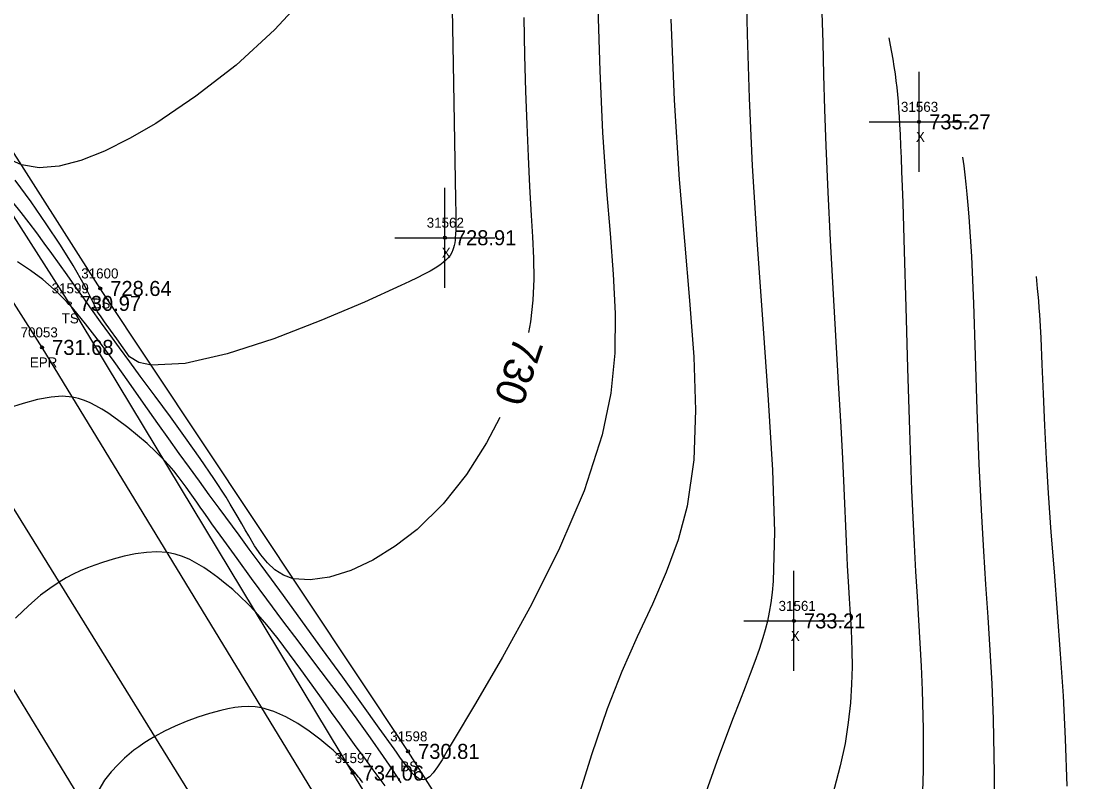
# Model space of a CAD drawing. Extents: x 1376587 to 1378239, y 1000335 to 1003031.
# Drawn here: x 1377746.5 to 1377851.9, y 1001005.8 to 1001081.8 of the extents above; entities that cross this region are included whole.
import ezdxf

# ---------------------------------------------------------------- set-up
doc = ezdxf.new("R2010")
doc.units = 0
for name, color, linetype in [('RD_DTM_BkLn1', 7, 'Continuous'), ('RD_DTM_BkLn2', 7, 'Continuous'), ('RD_DTM_BkLn_txCode', 7, 'Continuous'), ('RD_DTM_Major1', 7, 'Continuous'), ('RD_DTM_Major1_Lbl', 7, 'Continuous'), ('RD_DTM_Minor1', 7, 'Continuous'), ('RD_EX_Misc', 7, 'Continuous'), ('RD_EX_Misc_txCode', 7, 'Continuous'), ('RD_EX_Road', 7, 'Continuous'), ('RD_EX_Road_txCode', 7, 'Continuous'), ('RD_EX_TX_Misc_ELEV', 7, 'Continuous'), ('RD_EX_TX_Road_ELEV', 7, 'Continuous'), ('RD_SMD_Locator', 7, 'Continuous')]:
    doc.layers.add(name, color=color, linetype=linetype)

msp = doc.modelspace()

# ---------------------------------------------------------------- linework, layer by layer
at = {"layer": 'RD_DTM_BkLn1'}
msp.add_lwpolyline([(1377890.87, 1000795.13), (1377889.75, 1000797.09), (1377860.86, 1000844.28), (1377837.2, 1000883.19), (1377805.55, 1000935.32), (1377771.67, 1000991.28), (1377739.47, 1001043.28), (1377708.64, 1001094.78), (1377678.49, 1001143.97), (1377648.11, 1001195.1), (1377620.71, 1001239.29), (1377591.74, 1001287.41), (1377561.78, 1001336.41), (1377531.28, 1001387.73), (1377502.54, 1001434.98), (1377471.98, 1001486.19), (1377441.27, 1001536.58), (1377411.04, 1001586.42), (1377380.15, 1001637.79)], dxfattribs=at)
at = {"layer": 'RD_DTM_BkLn2'}
for points in [[(1377847.74, 1000893.92), (1377809.1, 1000958.58), (1377779.66, 1001006.67), (1377751.37, 1001053.61), (1377724.4, 1001095.78), (1377686.8, 1001159.89)], [(1377850.35, 1000896.66), (1377814.97, 1000961.96), (1377785.2, 1001008.84), (1377754.43, 1001055.1), (1377727.74, 1001096.98), (1377695.99, 1001144.52)]]:
    msp.add_lwpolyline(points, dxfattribs=at)
at = {"layer": 'RD_DTM_Major1'}
for points in [[(1377796.77, 1001082.19), (1377796.85, 1001078.39), (1377796.95, 1001074.83), (1377797.06, 1001071.47), (1377797.19, 1001068.29), (1377797.34, 1001065.28), (1377797.5, 1001062.4), (1377797.63, 1001060.25), (1377797.72, 1001058.14), (1377797.75, 1001056.04), (1377797.66, 1001053.93), (1377797.43, 1001051.77), (1377797.23, 1001050.7)], [(1377833.26, 1001080.13), (1377833.39, 1001079.42), (1377833.52, 1001078.71), (1377833.64, 1001078), (1377833.76, 1001077.28), (1377833.87, 1001076.56), (1377833.96, 1001075.84), (1377834.04, 1001075.17), (1377834.11, 1001074.48), (1377834.17, 1001073.78), (1377834.22, 1001073.06), (1377834.27, 1001072.3), (1377834.32, 1001071.5), (1377834.37, 1001070.48), (1377834.43, 1001069.36), (1377834.48, 1001068.14), (1377834.53, 1001066.8), (1377834.58, 1001065.3), (1377834.64, 1001063.65), (1377834.78, 1001058.83), (1377834.94, 1001053.22), (1377835.11, 1001047.15), (1377835.31, 1001040.95), (1377835.53, 1001034.95), (1377835.78, 1001029.49), (1377835.93, 1001026.81), (1377836.08, 1001024.32), (1377836.23, 1001021.96), (1377836.36, 1001019.66), (1377836.48, 1001017.35), (1377836.58, 1001014.96), (1377836.67, 1001011.06), (1377836.67, 1001006.94), (1377836.56, 1001002.74)], [(1377794.36, 1001042.2), (1377793.05, 1001039.67), (1377791.02, 1001036.5), (1377788.69, 1001033.58), (1377786.1, 1001031.02), (1377783.92, 1001029.34), (1377781.68, 1001027.96), (1377779.46, 1001026.92), (1377777.34, 1001026.25), (1377775.4, 1001025.97), (1377773.72, 1001026.09), (1377772.73, 1001026.44), (1377771.87, 1001026.97), (1377771.13, 1001027.67), (1377770.47, 1001028.48), (1377769.86, 1001029.39), (1377769.28, 1001030.37), (1377768.93, 1001030.97), (1377768.58, 1001031.59), (1377768.21, 1001032.22), (1377767.83, 1001032.87), (1377767.43, 1001033.54), (1377767.01, 1001034.24), (1377765.79, 1001036.12), (1377764.43, 1001038.11), (1377762.96, 1001040.18), (1377761.44, 1001042.27), (1377759.92, 1001044.34), (1377758.43, 1001046.35), (1377757.38, 1001047.78), (1377756.37, 1001049.16), (1377755.4, 1001050.5), (1377754.47, 1001051.78), (1377753.57, 1001053.03), (1377752.7, 1001054.25), (1377751.9, 1001055.36), (1377751.13, 1001056.45), (1377750.36, 1001057.53), (1377749.6, 1001058.58), (1377748.84, 1001059.62), (1377748.08, 1001060.65), (1377747.32, 1001061.67), (1377746.53, 1001062.69), (1377745.7, 1001063.71)]]:
    msp.add_lwpolyline(points, dxfattribs=at)
at = {"layer": 'RD_DTM_Minor1'}
for points in [[(1377789.54, 1001086.69), (1377789.7, 1001077.54), (1377789.93, 1001064), (1377789.96, 1001062.6), (1377789.96, 1001061.99), (1377789.96, 1001061.45), (1377789.96, 1001060.95), (1377789.94, 1001060.51), (1377789.92, 1001060.2), (1377789.9, 1001059.91), (1377789.86, 1001059.65), (1377789.81, 1001059.4), (1377789.75, 1001059.17), (1377789.68, 1001058.96), (1377789.56, 1001058.68), (1377789.4, 1001058.41), (1377789.21, 1001058.16), (1377788.97, 1001057.92), (1377788.69, 1001057.68), (1377788.36, 1001057.43), (1377787.91, 1001057.14), (1377787.39, 1001056.84), (1377786.79, 1001056.52), (1377786.1, 1001056.17), (1377785.33, 1001055.8), (1377784.46, 1001055.39), (1377780.84, 1001053.74), (1377776.48, 1001051.89), (1377771.78, 1001050.08), (1377767.13, 1001048.57), (1377762.92, 1001047.6), (1377759.54, 1001047.42), (1377758.28, 1001047.69), (1377757.36, 1001048.28), (1377756.72, 1001049.18), (1377756.08, 1001050.06), (1377755.46, 1001050.93), (1377754.85, 1001051.77), (1377754.51, 1001052.25), (1377754.16, 1001052.78), (1377753.85, 1001053.42), (1377753.53, 1001054.08), (1377753.19, 1001054.76), (1377752.82, 1001055.46), (1377751.73, 1001057.38), (1377750.45, 1001059.43), (1377749.03, 1001061.56), (1377747.51, 1001063.74), (1377745.93, 1001065.92)], [(1377818.95, 1001086.41), (1377819.08, 1001080.5), (1377819.29, 1001074.12), (1377819.6, 1001067.36), (1377820.09, 1001059.47), (1377820.66, 1001051.57), (1377821.2, 1001043.96), (1377821.62, 1001036.93), (1377821.82, 1001030.79), (1377821.7, 1001025.85), (1377821.59, 1001024.72), (1377821.46, 1001023.69), (1377821.3, 1001022.74), (1377821.11, 1001021.85), (1377820.9, 1001021), (1377820.66, 1001020.18), (1377820.29, 1001019.01), (1377819.87, 1001017.83), (1377819.4, 1001016.58), (1377818.89, 1001015.25), (1377818.32, 1001013.8), (1377817.69, 1001012.18), (1377816.23, 1001008.28), (1377814.61, 1001003.79)], [(1377775.35, 1001084.73), (1377771.86, 1001080.94), (1377768.01, 1001077.43), (1377763.99, 1001074.3), (1377759.97, 1001071.6), (1377757.36, 1001070.08), (1377754.86, 1001068.83), (1377752.5, 1001067.9), (1377750.31, 1001067.33), (1377748.32, 1001067.17), (1377746.55, 1001067.46), (1377745.24, 1001068.07)], [(1377804.17, 1001083.14), (1377804.36, 1001076.86), (1377804.63, 1001070.7), (1377805.02, 1001064.84), (1377805.38, 1001060.59), (1377805.71, 1001056.54), (1377805.91, 1001052.59), (1377805.86, 1001048.65), (1377805.46, 1001044.65), (1377804.61, 1001040.48), (1377802.79, 1001034.89), (1377800.34, 1001029.16), (1377797.54, 1001023.53), (1377794.65, 1001018.27), (1377791.95, 1001013.64), (1377789.72, 1001009.89), (1377789.12, 1001008.88), (1377788.6, 1001008.01), (1377788.13, 1001007.28), (1377787.71, 1001006.71), (1377787.33, 1001006.3), (1377786.97, 1001006.06), (1377786.71, 1001006), (1377786.45, 1001006.03), (1377786.19, 1001006.16), (1377785.93, 1001006.36), (1377785.65, 1001006.63), (1377785.35, 1001006.98), (1377785.13, 1001007.26), (1377784.9, 1001007.57), (1377784.65, 1001007.9), (1377784.38, 1001008.27), (1377784.1, 1001008.66), (1377783.81, 1001009.08), (1377782.32, 1001011.16), (1377780.58, 1001013.59), (1377778.66, 1001016.25), (1377776.65, 1001019.03), (1377774.64, 1001021.79), (1377772.73, 1001024.42), (1377771.53, 1001026.06), (1377770.41, 1001027.59), (1377769.33, 1001029.05), (1377768.3, 1001030.45), (1377766.32, 1001033.15), (1377765.33, 1001034.49), (1377764.34, 1001035.83), (1377763.34, 1001037.21), (1377762.32, 1001038.61), (1377761.27, 1001040.07), (1377760.19, 1001041.6), (1377758.76, 1001043.63), (1377757.3, 1001045.72), (1377755.82, 1001047.79), (1377754.37, 1001049.76), (1377752.96, 1001051.57), (1377751.64, 1001053.15), (1377751.44, 1001053.37), (1377751.25, 1001053.58), (1377751.05, 1001053.79), (1377750.86, 1001054), (1377750.66, 1001054.2), (1377750.46, 1001054.39), (1377750.36, 1001054.49), (1377750.26, 1001054.59), (1377750.16, 1001054.69), (1377750.05, 1001054.79), (1377749.95, 1001054.88), (1377749.84, 1001054.98), (1377748.69, 1001055.98), (1377747.45, 1001056.91), (1377746.16, 1001057.75)], [(1377826.56, 1001082.65), (1377826.64, 1001079.69), (1377826.72, 1001076.46), (1377826.81, 1001073), (1377826.94, 1001069.35), (1377827.14, 1001064.71), (1377827.38, 1001059.93), (1377827.65, 1001055.11), (1377828.2, 1001045.68), (1377828.45, 1001041.27), (1377828.61, 1001038.12), (1377828.75, 1001035.15), (1377828.99, 1001029.8), (1377829.1, 1001027.42), (1377829.22, 1001025.24), (1377829.29, 1001024.12), (1377829.35, 1001023.05), (1377829.42, 1001022.01), (1377829.47, 1001020.99), (1377829.52, 1001019.97), (1377829.55, 1001018.93), (1377829.57, 1001017.28), (1377829.53, 1001015.54), (1377829.41, 1001013.7), (1377829.2, 1001011.74), (1377828.87, 1001009.64), (1377828.4, 1001007.4), (1377827.42, 1001003.69)], [(1377811.47, 1001082.01), (1377811.8, 1001073.91), (1377812.29, 1001066), (1377812.81, 1001059.81), (1377813.34, 1001053.89), (1377813.76, 1001048.26), (1377813.94, 1001042.95), (1377813.76, 1001037.96), (1377813.09, 1001033.33), (1377812.19, 1001029.99), (1377811, 1001026.76), (1377809.62, 1001023.56), (1377808.11, 1001020.28), (1377806.57, 1001016.82), (1377805.08, 1001013.09), (1377803.53, 1001008.5), (1377802.08, 1001003.81)], [(1377840.62, 1001068.22), (1377840.73, 1001067.34), (1377840.85, 1001066.45), (1377840.96, 1001065.51), (1377841.06, 1001064.51), (1377841.16, 1001063.44), (1377841.26, 1001062.27), (1377841.5, 1001058.29), (1377841.7, 1001053.59), (1377841.88, 1001048.4), (1377842.06, 1001042.96), (1377842.26, 1001037.53), (1377842.5, 1001032.35), (1377842.7, 1001028.84), (1377842.92, 1001025.5), (1377843.14, 1001022.24), (1377843.35, 1001018.97), (1377843.53, 1001015.6), (1377843.67, 1001012.05), (1377843.79, 1001006.63), (1377843.81, 1001000.93)], [(1377847.98, 1001056.3), (1377848.09, 1001055.11), (1377848.15, 1001054.49), (1377848.2, 1001053.85), (1377848.25, 1001053.17), (1377848.3, 1001052.46), (1377848.43, 1001050.15), (1377848.55, 1001047.5), (1377848.68, 1001044.57), (1377848.82, 1001041.41), (1377848.98, 1001038.08), (1377849.18, 1001034.63), (1377849.45, 1001030.74), (1377849.76, 1001026.77), (1377850.08, 1001022.72), (1377850.39, 1001018.59), (1377850.67, 1001014.38), (1377850.88, 1001010.1), (1377851.03, 1001005.36)], [(1377784.5, 1001005.71), (1377783.64, 1001007.03), (1377782.75, 1001008.34), (1377781.45, 1001010.2), (1377780.1, 1001012.07), (1377778.7, 1001013.95), (1377777.26, 1001015.86), (1377775.79, 1001017.79), (1377774.3, 1001019.76), (1377772.69, 1001021.9), (1377771.09, 1001024.04), (1377769.55, 1001026.12), (1377768.1, 1001028.11), (1377766.77, 1001029.95), (1377765.59, 1001031.59), (1377765.18, 1001032.18), (1377764.79, 1001032.73), (1377764.42, 1001033.25), (1377764.08, 1001033.75), (1377763.74, 1001034.22), (1377763.42, 1001034.68), (1377763.02, 1001035.24), (1377762.62, 1001035.79), (1377762.21, 1001036.32), (1377761.78, 1001036.86), (1377761.31, 1001037.4), (1377760.8, 1001037.96), (1377759.99, 1001038.77), (1377759.11, 1001039.59), (1377758.16, 1001040.41), (1377757.17, 1001041.21), (1377756.17, 1001041.97), (1377755.18, 1001042.66), (1377754.59, 1001043.03), (1377754, 1001043.37), (1377753.42, 1001043.67), (1377752.84, 1001043.91), (1377752.25, 1001044.11), (1377751.65, 1001044.24), (1377751.32, 1001044.28), (1377750.97, 1001044.31), (1377750.62, 1001044.32), (1377750.27, 1001044.31), (1377749.9, 1001044.28), (1377749.52, 1001044.24), (1377748.17, 1001044), (1377746.72, 1001043.62), (1377745.22, 1001043.13)], [(1377782.9, 1001005.4), (1377781.72, 1001007), (1377780.86, 1001008.16), (1377780.02, 1001009.31), (1377779.19, 1001010.45), (1377778.37, 1001011.59), (1377777.54, 1001012.74), (1377776.7, 1001013.92), (1377775.6, 1001015.46), (1377774.48, 1001017.02), (1377773.34, 1001018.57), (1377772.21, 1001020.07), (1377771.07, 1001021.48), (1377769.95, 1001022.77), (1377769.19, 1001023.58), (1377768.43, 1001024.33), (1377767.67, 1001025.01), (1377766.93, 1001025.63), (1377766.19, 1001026.21), (1377765.45, 1001026.75), (1377764.77, 1001027.21), (1377764.08, 1001027.63), (1377763.38, 1001028), (1377762.66, 1001028.31), (1377761.91, 1001028.55), (1377761.12, 1001028.71), (1377760.1, 1001028.78), (1377759.04, 1001028.73), (1377757.94, 1001028.58), (1377756.83, 1001028.35), (1377755.73, 1001028.06), (1377754.65, 1001027.72), (1377753.89, 1001027.46), (1377753.15, 1001027.18), (1377752.42, 1001026.88), (1377751.71, 1001026.54), (1377751.01, 1001026.18), (1377750.31, 1001025.76), (1377749.38, 1001025.13), (1377748.46, 1001024.44), (1377747.58, 1001023.69), (1377746.75, 1001022.92), (1377745.97, 1001022.15)], [(1377780.67, 1001005.74), (1377780.52, 1001005.94), (1377780.37, 1001006.13), (1377780.22, 1001006.31), (1377780.04, 1001006.53), (1377779.85, 1001006.75), (1377779.67, 1001006.96), (1377779.49, 1001007.17), (1377779.3, 1001007.37), (1377779.11, 1001007.58), (1377778.85, 1001007.85), (1377778.58, 1001008.12), (1377778.3, 1001008.39), (1377778.01, 1001008.67), (1377777.7, 1001008.95), (1377777.38, 1001009.23), (1377776.39, 1001010.05), (1377775.31, 1001010.87), (1377774.17, 1001011.63), (1377772.98, 1001012.3), (1377771.78, 1001012.83), (1377770.59, 1001013.18), (1377769.9, 1001013.29), (1377769.22, 1001013.32), (1377768.55, 1001013.3), (1377767.87, 1001013.22), (1377767.18, 1001013.1), (1377766.49, 1001012.94), (1377765.35, 1001012.63), (1377764.19, 1001012.26), (1377763.03, 1001011.83), (1377761.91, 1001011.36), (1377760.85, 1001010.86), (1377759.87, 1001010.33), (1377759.31, 1001010), (1377758.78, 1001009.66), (1377758.28, 1001009.31), (1377757.8, 1001008.95), (1377757.33, 1001008.57), (1377756.87, 1001008.16), (1377756.19, 1001007.51), (1377755.52, 1001006.78), (1377754.87, 1001005.96), (1377754.28, 1001005.01)]]:
    msp.add_lwpolyline(points, dxfattribs=at)
at = {"layer": 'RD_EX_Misc'}
for p, q in [((1377836.28, 1001066.75), (1377836.28, 1001076.75)), ((1377831.28, 1001071.75), (1377841.28, 1001071.75)), ((1377788.88, 1001055.17), (1377788.88, 1001065.17)), ((1377783.88, 1001060.17), (1377793.88, 1001060.17)), ((1377823.77, 1001016.88), (1377823.77, 1001026.88)), ((1377818.77, 1001021.88), (1377828.77, 1001021.88))]:
    msp.add_line(p, q, dxfattribs=at)
at = {"layer": 'RD_EX_Road'}
for points in [[(1377899.67, 1000800.29), (1377898.72, 1000801.84), (1377870.31, 1000849.94), (1377847.28, 1000887.89), (1377815.15, 1000940.58), (1377781.51, 1000995.26), (1377748.62, 1001049.21), (1377716.58, 1001099.53), (1377686.67, 1001148.78), (1377656.47, 1001199.11), (1377629.54, 1001244.18), (1377599.89, 1001292.67), (1377570.87, 1001341.43), (1377539.83, 1001392.47), (1377511.01, 1001440.31), (1377480.72, 1001490), (1377449.73, 1001541.49), (1377420.9, 1001591.95), (1377390.45, 1001644.41)], [(1377883.75, 1000788.5), (1377882.63, 1000790.22), (1377852.26, 1000839.6), (1377828.46, 1000879.31), (1377797, 1000930.66), (1377763.07, 1000986.65), (1377731.87, 1001037.81), (1377700.31, 1001089.98), (1377670.43, 1001138.24), (1377639.73, 1001190.03), (1377611.89, 1001234.23), (1377582.78, 1001282.57), (1377552.22, 1001331.03), (1377522.24, 1001382.35), (1377494.26, 1001430.19), (1377463.17, 1001481.14), (1377433.42, 1001531.29), (1377403.14, 1001580.98), (1377371.36, 1001632.19)]]:
    msp.add_lwpolyline(points, dxfattribs=at)
at = {"layer": 'RD_SMD_Locator'}
for centre in [(1377836.28, 1001071.75), (1377788.88, 1001060.17), (1377754.43, 1001055.1), (1377751.37, 1001053.61), (1377748.62, 1001049.21), (1377823.77, 1001021.88), (1377785.2, 1001008.84), (1377779.66, 1001006.67)]:
    msp.add_circle(centre, 0.15, dxfattribs=at)

# ---------------------------------------------------------------- texts
at = {"layer": 'RD_DTM_BkLn_txCode'}
for s, p in [('31600', (1377752.53, 1001056.1)), ('31599', (1377749.57, 1001054.61)), ('BS', (1377753.65, 1001053.1)), ('TS', (1377750.57, 1001051.61)), ('31598', (1377783.41, 1001009.84)), ('31597', (1377777.86, 1001007.67)), ('BS', (1377784.42, 1001006.84))]:
    msp.add_text(s, height=1, dxfattribs=at).set_placement(p)
at = {"layer": 'RD_DTM_Major1_Lbl'}
msp.add_text('730', height=3, rotation=251.2795, dxfattribs=at).set_placement((1377795.91, 1001050.48))
at = {"layer": 'RD_EX_Misc_txCode'}
for s, p in [('31563', (1377834.46, 1001072.75)), ('X', (1377835.96, 1001069.75)), ('31562', (1377787.06, 1001061.17)), ('X', (1377788.56, 1001058.17)), ('31561', (1377822.23, 1001022.88)), ('X', (1377823.45, 1001019.88))]:
    msp.add_text(s, height=1, dxfattribs=at).set_placement(p)
at = {"layer": 'RD_EX_Road_txCode'}
for s, p in [('70053', (1377746.47, 1001050.21)), ('EPR', (1377747.39, 1001047.21))]:
    msp.add_text(s, height=1, dxfattribs=at).set_placement(p)
at = {"layer": 'RD_EX_TX_Misc_ELEV'}
for s, p in [('735.27', (1377837.28, 1001071)), ('728.91', (1377789.88, 1001059.42)), ('728.64', (1377755.43, 1001054.35)), ('730.97', (1377752.37, 1001052.86)), ('733.21', (1377824.77, 1001021.13)), ('730.81', (1377786.2, 1001008.09)), ('734.06', (1377780.66, 1001005.92))]:
    msp.add_text(s, height=1.5, dxfattribs=at).set_placement(p)
at = {"layer": 'RD_EX_TX_Road_ELEV'}
msp.add_text('731.68', height=1.5, dxfattribs=at).set_placement((1377749.62, 1001048.46))

doc.saveas('drawing.dxf')
